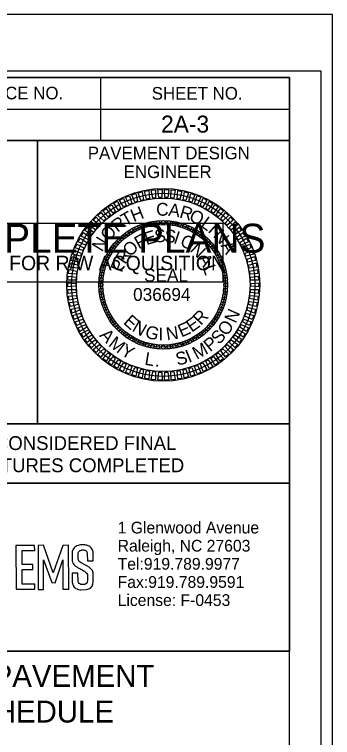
# Model space of a CAD drawing. Extents: x 958711 to 962106, y 831169 to 840840.
# Drawn here: x 960268.7 to 960394.8, y 838104 to 838391.1 of the extents above; entities that cross this region are included whole.
import ezdxf

# ---------------------------------------------------------------- set-up
doc = ezdxf.new("R2010")
doc.units = 0
for name, color, linetype in [('Old_Level_1', 7, 'Continuous'), ('Old_Level_2', 7, 'Continuous'), ('Old_Level_50', 7, 'Continuous'), ('Old_Level_58', 7, 'Continuous'), ('Sheet Data Field CELL', 7, 'Continuous'), ('Sheet PE Seal Cell', 7, 'Continuous'), ('Sheet Plot Border Inside CELL', 7, 'Continuous'), ('Sheet Plot Border Outside CELL', 7, 'Continuous'), ('Sheet Sticker Exception Certification CELL', 7, 'Continuous'), ('Sheet Sticker Incomplete CELL', 7, 'Continuous'), ('Sheet Typical CELL', 7, 'Continuous')]:
    doc.layers.add(name, color=color, linetype=linetype)

msp = doc.modelspace()

# ---------------------------------------------------------------- linework, layer by layer
at = {"layer": 'Old_Level_1'}
for points in [[(960276.67, 838180.33), (960269.28, 838180.32), (960269.3, 838162.89), (960276.77, 838162.9), (960276.77, 838164.87), (960271.73, 838164.87), (960271.72, 838170.71), (960275.94, 838170.71), (960275.93, 838172.79), (960271.68, 838172.78), (960271.68, 838178.28), (960276.69, 838178.29)], [(960284.05, 838169.48), (960280.23, 838180.4), (960278.02, 838180.29), (960278.11, 838162.83), (960280.22, 838162.84), (960280.16, 838174.52), (960283.43, 838165.53), (960284.78, 838165.5), (960287.84, 838174.63), (960287.89, 838162.91), (960290.17, 838162.92), (960290.1, 838180.34), (960287.8, 838180.33)], [(960297.57, 838174.17), (960299.88, 838174.17), (960299.88, 838177.65), (960299.69, 838178.35), (960299.4, 838178.94), (960299.11, 838179.33), (960298.74, 838179.69), (960298.3, 838179.97), (960297.87, 838180.14), (960297.87, 838180.14), (960297.41, 838180.34), (960296.93, 838180.46), (960296.61, 838180.54), (960294.86, 838180.5), (960294.33, 838180.41), (960293.87, 838180.33), (960293.41, 838180.09), (960293.01, 838179.88), (960292.61, 838179.6), (960292.3, 838179.28), (960292.06, 838178.92), (960291.87, 838178.52), (960291.61, 838177.83), (960291.56, 838177.31), (960291.56, 838174.14), (960291.68, 838173.67), (960291.91, 838173.17), (960292.19, 838172.76), (960292.49, 838172.45), (960292.94, 838172.1), (960293.39, 838171.76), (960293.68, 838171.54), (960294.16, 838171.31), (960294.65, 838171.09), (960295.04, 838170.83), (960295.48, 838170.55), (960296, 838170.28), (960296.44, 838170.06), (960296.87, 838169.75), (960297.18, 838169.45), (960297.43, 838169.21), (960297.58, 838168.73), (960297.67, 838168.43), (960297.64, 838166.2), (960297.48, 838165.71), (960297.23, 838165.29), (960296.91, 838165), (960296.55, 838164.84), (960296.21, 838164.77), (960295.25, 838164.75), (960294.93, 838164.84), (960294.6, 838165.03), (960294.27, 838165.23), (960294.13, 838165.56), (960293.98, 838165.9), (960293.87, 838166.16), (960293.83, 838169.28), (960291.5, 838169.25), (960291.54, 838165.54), (960291.66, 838165.26), (960291.93, 838164.39), (960292.1, 838164.1), (960292.36, 838163.78), (960292.74, 838163.41), (960293.04, 838163.22), (960293.48, 838163.03), (960293.63, 838162.97), (960294.06, 838162.79), (960294.6, 838162.73), (960294.99, 838162.69), (960297.13, 838162.75), (960297.73, 838162.89), (960298.55, 838163.26), (960298.83, 838163.39), (960299.45, 838164.18), (960299.79, 838164.97), (960299.94, 838165.68), (960299.89, 838169.1), (960299.88, 838169.57), (960299.75, 838169.95), (960299.56, 838170.3), (960299.02, 838171.06), (960298.31, 838171.62), (960297.34, 838172.2), (960296.59, 838172.64), (960295.13, 838173.41), (960294.37, 838173.97), (960294.05, 838174.39), (960293.97, 838174.67), (960293.89, 838174.96), (960293.94, 838177.39), (960294.06, 838177.64), (960294.19, 838177.9), (960294.36, 838178.05), (960294.59, 838178.25), (960294.85, 838178.35), (960295.11, 838178.46), (960295.26, 838178.43), (960295.27, 838178.51), (960296.23, 838178.49), (960296.51, 838178.38), (960296.79, 838178.27), (960297.07, 838178.16), (960297.19, 838177.97), (960297.38, 838177.69), (960297.47, 838177.41), (960297.56, 838177.14), (960297.56, 838176.83)]]:
    msp.add_lwpolyline(points, close=True, dxfattribs=at)
at = {"layer": 'Old_Level_50'}
msp.add_line((960177.74, 838138.32), (960377.79, 838138.32), dxfattribs=at)
at = {"layer": 'Old_Level_58'}
msp.add_lwpolyline([(960177.75, 838205.02), (960377.8, 838205.02), (960377.8, 838138.32), (960177.75, 838138.32)], close=True, dxfattribs=at)
at = {"layer": 'Sheet PE Seal Cell'}
for points in [[(960314.16, 838315.68), (960312.74, 838318.53), (960314.28, 838319.12), (960315.23, 838316.12)], [(960316.42, 838316.54), (960315.21, 838319.49), (960316.78, 838319.97), (960317.52, 838316.91)], [(960318.73, 838317.25), (960317.73, 838320.27), (960319.34, 838320.64), (960319.86, 838317.54)], [(960321.09, 838317.79), (960320.3, 838320.88), (960321.93, 838321.13), (960322.24, 838318)], [(960323.48, 838318.17), (960322.91, 838321.3), (960324.55, 838321.44), (960324.64, 838318.3)], [(960325.89, 838318.38), (960325.54, 838321.54), (960327.19, 838321.57), (960327.06, 838318.43)], [(960328.31, 838318.42), (960328.18, 838321.6), (960329.83, 838321.51), (960329.48, 838318.39)], [(960330.73, 838318.29), (960330.82, 838321.47), (960332.46, 838321.27), (960331.89, 838318.18)], [(960333.13, 838317.99), (960333.44, 838321.16), (960335.06, 838320.85), (960334.28, 838317.8)], [(960335.51, 838317.53), (960336.04, 838320.67), (960337.63, 838320.24), (960336.64, 838317.26)], [(960337.84, 838316.9), (960338.59, 838320), (960340.15, 838319.46), (960338.95, 838316.55)], [(960340.13, 838316.11), (960341.1, 838319.15), (960342.61, 838318.5), (960341.21, 838315.68)], [(960309.84, 838313.48), (960308.05, 838316.11), (960309.49, 838316.91), (960310.85, 838314.07)], [(960311.96, 838314.66), (960310.35, 838317.4), (960311.85, 838318.1), (960313.01, 838315.17)], [(960342.36, 838315.17), (960343.53, 838318.12), (960345, 838317.38), (960343.41, 838314.66)], [(960344.51, 838314.07), (960345.89, 838316.94), (960347.3, 838316.09), (960345.53, 838313.49)], [(960305.88, 838310.71), (960303.74, 838313.06), (960305.05, 838314.06), (960306.79, 838311.44)], [(960307.81, 838312.17), (960305.84, 838314.66), (960307.22, 838315.56), (960308.78, 838312.83)], [(960346.59, 838312.82), (960348.16, 838315.58), (960349.51, 838314.64), (960347.56, 838312.17)], [(960348.57, 838311.43), (960350.33, 838314.08), (960351.61, 838313.04), (960349.49, 838310.72)], [(960302.34, 838307.42), (960299.89, 838309.45), (960301.06, 838310.61), (960303.14, 838308.26)], [(960304.05, 838309.13), (960301.75, 838311.32), (960302.99, 838312.4), (960304.91, 838309.91)], [(960350.45, 838309.9), (960352.39, 838312.42), (960353.6, 838311.3), (960351.32, 838309.13)], [(960352.22, 838308.25), (960354.33, 838310.63), (960355.46, 838309.42), (960353.03, 838307.42)], [(960300.75, 838305.59), (960298.16, 838307.45), (960299.25, 838308.69), (960301.49, 838306.49)], [(960353.87, 838306.48), (960356.14, 838308.71), (960357.18, 838307.42), (960354.62, 838305.59)], [(960297.97, 838301.63), (960295.15, 838303.11), (960296.05, 838304.49), (960298.58, 838302.62)], [(960299.29, 838303.66), (960296.58, 838305.33), (960297.58, 838306.64), (960299.97, 838304.61)], [(960355.39, 838304.6), (960357.82, 838306.66), (960358.76, 838305.31), (960356.08, 838303.66)], [(960356.78, 838302.62), (960359.34, 838304.5), (960360.19, 838303.09), (960357.4, 838301.63)], [(960296.8, 838299.51), (960293.88, 838300.79), (960294.68, 838302.23), (960297.34, 838300.55)], [(960358.02, 838300.54), (960360.71, 838302.24), (960361.46, 838300.77), (960358.57, 838299.51)], [(960295.77, 838297.32), (960292.78, 838298.39), (960293.47, 838299.88), (960296.24, 838298.39)], [(960359.12, 838298.38), (960361.92, 838299.89), (960362.56, 838298.38), (960359.6, 838297.32)], [(960294.91, 838295.06), (960291.84, 838295.92), (960292.43, 838297.46), (960295.3, 838296.16)], [(960360.06, 838296.15), (960362.96, 838297.47), (960363.5, 838295.91), (960360.47, 838295.06)], [(960294.2, 838292.75), (960291.08, 838293.39), (960291.56, 838294.97), (960294.51, 838293.87)], [(960360.85, 838293.87), (960363.83, 838294.97), (960364.26, 838293.38), (960361.18, 838292.75)], [(960293.65, 838290.39), (960290.5, 838290.81), (960290.87, 838292.42), (960293.89, 838291.53)], [(960361.47, 838291.53), (960364.53, 838292.42), (960364.84, 838290.8), (960361.72, 838290.39)], [(960293.06, 838285.59), (960289.87, 838285.57), (960290.02, 838287.21), (960293.13, 838286.75)], [(960293.27, 838288), (960290.09, 838288.2), (960290.35, 838289.83), (960293.42, 838289.15)], [(960361.93, 838289.15), (960365.04, 838289.83), (960365.24, 838288.2), (960362.1, 838288)], [(960362.23, 838286.75), (960365.38, 838287.21), (960365.46, 838285.56), (960362.32, 838285.59)], [(960293.01, 838283.17), (960289.84, 838282.93), (960289.87, 838284.58), (960293.01, 838284.33)], [(960362.35, 838284.33), (960365.53, 838284.57), (960365.5, 838282.92), (960362.36, 838283.17)], [(960293.14, 838280.75), (960289.99, 838280.29), (960289.9, 838281.94), (960293.05, 838281.91)], [(960362.31, 838281.91), (960365.49, 838281.93), (960365.35, 838280.29), (960362.23, 838280.75)], [(960293.43, 838278.35), (960290.32, 838277.67), (960290.12, 838279.31), (960293.26, 838279.5)], [(960362.1, 838279.5), (960365.27, 838279.3), (960365.01, 838277.67), (960361.94, 838278.35)], [(960293.89, 838275.97), (960290.84, 838275.08), (960290.52, 838276.7), (960293.64, 838277.11)], [(960361.72, 838277.11), (960364.87, 838276.69), (960364.5, 838275.08), (960361.48, 838275.97)], [(960294.52, 838273.64), (960291.53, 838272.53), (960291.11, 838274.12), (960294.19, 838274.75)], [(960361.17, 838274.75), (960364.29, 838274.11), (960363.8, 838272.53), (960360.86, 838273.63)], [(960295.3, 838271.35), (960292.4, 838270.03), (960291.87, 838271.59), (960294.9, 838272.44)], [(960296.25, 838269.12), (960293.45, 838267.61), (960292.8, 838269.12), (960295.77, 838270.18)], [(960359.59, 838270.18), (960362.59, 838269.11), (960361.89, 838267.62), (960359.12, 838269.11)], [(960360.46, 838272.44), (960363.53, 838271.58), (960362.93, 838270.04), (960360.07, 838271.34)], [(960297.34, 838266.96), (960294.66, 838265.26), (960293.91, 838266.73), (960296.79, 838267.99)], [(960358.57, 838267.99), (960361.48, 838266.71), (960360.68, 838265.27), (960358.03, 838266.96)], [(960298.59, 838264.89), (960296.03, 838263), (960295.18, 838264.41), (960297.97, 838265.87)], [(960357.39, 838265.87), (960360.21, 838264.39), (960359.31, 838263.01), (960356.78, 838264.88)], [(960299.98, 838262.9), (960297.55, 838260.84), (960296.61, 838262.19), (960299.29, 838263.84)], [(960301.5, 838261.02), (960299.22, 838258.79), (960298.19, 838260.08), (960300.74, 838261.91)], [(960354.61, 838261.91), (960357.2, 838260.06), (960356.12, 838258.81), (960353.87, 838261.01)], [(960356.07, 838263.84), (960358.78, 838262.17), (960357.79, 838260.86), (960355.39, 838262.9)], [(960303.15, 838259.25), (960301.03, 838256.87), (960299.91, 838258.08), (960302.33, 838260.08)], [(960353.03, 838260.09), (960355.48, 838258.05), (960354.31, 838256.89), (960352.22, 838259.24)], [(960304.92, 838257.6), (960302.97, 838255.08), (960301.77, 838256.2), (960304.05, 838258.37)], [(960306.8, 838256.07), (960305.03, 838253.42), (960303.75, 838254.46), (960305.87, 838256.78)], [(960349.49, 838256.79), (960351.63, 838254.44), (960350.31, 838253.44), (960348.57, 838256.07)], [(960351.31, 838258.38), (960353.62, 838256.18), (960352.37, 838255.1), (960350.45, 838257.59)], [(960308.78, 838254.68), (960307.2, 838251.92), (960305.85, 838252.86), (960307.81, 838255.33)], [(960310.85, 838253.44), (960309.47, 838250.57), (960308.06, 838251.42), (960309.84, 838254.01)], [(960313.01, 838252.34), (960311.83, 838249.38), (960310.36, 838250.13), (960311.96, 838252.84)], [(960343.4, 838252.84), (960345.01, 838250.1), (960343.52, 838249.4), (960342.36, 838252.33)], [(960345.52, 838254.02), (960347.32, 838251.39), (960345.87, 838250.59), (960344.52, 838253.43)], [(960347.55, 838255.33), (960349.53, 838252.84), (960348.14, 838251.94), (960346.59, 838254.68)], [(960315.23, 838251.39), (960314.27, 838248.35), (960312.75, 838249), (960314.15, 838251.82)], [(960317.52, 838250.6), (960316.77, 838247.5), (960315.21, 838248.04), (960316.41, 838250.95)], [(960319.86, 838249.97), (960319.33, 838246.83), (960317.73, 838247.26), (960318.73, 838250.25)], [(960336.63, 838250.25), (960337.64, 838247.23), (960336.03, 838246.86), (960335.51, 838249.96)], [(960338.95, 838250.96), (960340.16, 838248.01), (960338.58, 838247.53), (960337.84, 838250.59)], [(960341.21, 838251.82), (960342.62, 838248.97), (960341.08, 838248.38), (960340.13, 838251.38)], [(960322.24, 838249.51), (960321.92, 838246.34), (960320.3, 838246.65), (960321.09, 838249.7)], [(960324.64, 838249.21), (960324.55, 838246.03), (960322.91, 838246.23), (960323.48, 838249.32)], [(960327.05, 838249.08), (960327.18, 838245.9), (960325.54, 838245.99), (960325.89, 838249.12)], [(960329.47, 838249.12), (960329.83, 838245.96), (960328.18, 838245.93), (960328.31, 838249.07)], [(960331.88, 838249.33), (960332.46, 838246.2), (960330.81, 838246.06), (960330.73, 838249.2)], [(960334.28, 838249.71), (960335.06, 838246.62), (960333.44, 838246.37), (960333.13, 838249.5)]]:
    msp.add_lwpolyline(points, close=True, dxfattribs=at)
for centre, radius in [((960327.68, 838283.75), 38.25), ((960327.68, 838283.75), 36.34), ((960327.68, 838283.75), 34.43), ((960327.68, 838283.75), 25.5), ((960327.68, 838283.75), 24.74), ((960327.68, 838283.75), 23.97), ((960319.22, 838307), 0.765), ((960321.28, 838307.64), 0.765), ((960323.39, 838308.11), 0.765), ((960325.53, 838308.39), 0.765), ((960327.68, 838308.49), 0.765), ((960329.84, 838308.39), 0.765), ((960331.98, 838308.11), 0.765), ((960334.09, 838307.64), 0.765), ((960336.14, 838307), 0.765), ((960313.49, 838304.01), 0.765), ((960315.31, 838305.17), 0.765), ((960317.23, 838306.17), 0.765), ((960338.14, 838306.17), 0.765), ((960340.05, 838305.17), 0.765), ((960341.87, 838304.01), 0.765), ((960310.19, 838301.24), 0.765), ((960311.78, 838302.7), 0.765), ((960343.58, 838302.7), 0.765), ((960345.17, 838301.24), 0.765), ((960307.42, 838297.94), 0.765), ((960308.73, 838299.65), 0.765), ((960346.63, 838299.65), 0.765), ((960347.95, 838297.94), 0.765), ((960306.26, 838296.12), 0.765), ((960349.11, 838296.12), 0.765), ((960304.44, 838292.21), 0.765), ((960305.26, 838294.2), 0.765), ((960350.1, 838294.2), 0.765), ((960350.93, 838292.21), 0.765), ((960303.79, 838290.15), 0.765), ((960351.58, 838290.15), 0.765), ((960303.32, 838288.05), 0.765), ((960352.04, 838288.05), 0.765), ((960302.95, 838283.75), 0.765), ((960303.04, 838285.91), 0.765), ((960352.33, 838285.91), 0.765), ((960352.42, 838283.75), 0.765), ((960303.04, 838281.59), 0.765), ((960352.33, 838281.59), 0.765), ((960303.32, 838279.45), 0.765), ((960352.04, 838279.45), 0.765), ((960303.79, 838277.35), 0.765), ((960304.44, 838275.29), 0.765), ((960350.93, 838275.29), 0.765), ((960351.58, 838277.35), 0.765), ((960305.26, 838273.3), 0.765), ((960350.1, 838273.3), 0.765), ((960306.26, 838271.38), 0.765), ((960307.42, 838269.56), 0.765), ((960347.95, 838269.56), 0.765), ((960349.11, 838271.38), 0.765), ((960308.73, 838267.85), 0.765), ((960346.63, 838267.85), 0.765), ((960310.19, 838266.26), 0.765), ((960311.78, 838264.8), 0.765), ((960313.49, 838263.49), 0.765), ((960341.87, 838263.49), 0.765), ((960343.58, 838264.8), 0.765), ((960345.17, 838266.26), 0.765), ((960315.31, 838262.33), 0.765), ((960317.23, 838261.33), 0.765), ((960338.14, 838261.33), 0.765), ((960340.05, 838262.33), 0.765), ((960319.22, 838260.5), 0.765), ((960321.28, 838259.86), 0.765), ((960323.39, 838259.39), 0.765), ((960325.53, 838259.11), 0.765), ((960327.68, 838259.01), 0.765), ((960329.84, 838259.11), 0.765), ((960331.98, 838259.39), 0.765), ((960334.09, 838259.86), 0.765), ((960336.14, 838260.5), 0.765)]:
    msp.add_circle(centre, radius, dxfattribs=at)
at = {"layer": 'Sheet Plot Border Inside CELL'}
msp.add_lwpolyline([(960390.3, 838368.62), (958723.8, 838368.62), (958723.8, 837313.52), (960390.3, 837313.52)], close=True, dxfattribs=at)
at = {"layer": 'Sheet Plot Border Outside CELL'}
msp.add_lwpolyline([(960394.8, 838391.07), (958710.8, 838391.07), (958710.8, 837291.07), (960394.8, 837291.07)], close=True, dxfattribs=at)
at = {"layer": 'Sheet Sticker Exception Certification CELL'}
for p, q in [((960177.75, 838228.52), (960377.79, 838228.52)), ((960377.79, 838228.5), (960377.79, 838205)), ((960377.79, 838205.02), (960177.75, 838205.02))]:
    msp.add_line(p, q, dxfattribs=at)
at = {"layer": 'Sheet Sticker Incomplete CELL'}
msp.add_lwpolyline([(960204.3, 838284.77), (960204.3, 838308.27), (960351.3, 838308.27), (960351.3, 838284.77)], close=True, dxfattribs=at)
at = {"layer": 'Sheet Typical CELL'}
for p, q in [((960302.8, 838366.02), (960302.8, 838341.02)), ((960177.75, 838353.52), (960377.8, 838353.52)), ((960277.8, 838341.02), (960277.8, 838228.57))]:
    msp.add_line(p, q, dxfattribs=at)
for points in [[(960377.8, 838366.07), (958877.8, 838366.07), (958877.8, 837316.07), (960377.8, 837316.07)], [(960177.75, 838366.07), (960377.8, 838366.07), (960377.8, 838341.02), (960177.75, 838341.02)], [(960177.75, 838341.02), (960277.8, 838341.02), (960277.8, 838228.52), (960177.75, 838228.52)], [(960277.8, 838341.02), (960377.8, 838341.02), (960377.8, 838228.52), (960277.8, 838228.52)]]:
    msp.add_lwpolyline(points, close=True, dxfattribs=at)

# ---------------------------------------------------------------- texts
at = {"layer": 'Old_Level_1'}
for s, rotation, p in [('N', 66.0368, (960356.35, 838268.2)), ('O', 55.3117, (960352.96, 838263.13)), ('A', 312.9092, (960302.12, 838263.49)), ('S', 47.1983, (960349.8, 838259.77)), ('M', 321.9567, (960305.62, 838259.72)), ('P', 39.2185, (960346.25, 838256.94)), ('Y', 332.6628, (960310.47, 838256.04)), ('M', 28.5124, (960340.95, 838253.95)), ('L', 351.0246, (960320.07, 838252.03)), ('S', 14.4591, (960333.32, 838251.62)), ('I', 22.5724, (960337.79, 838252.74)), ('.', 358.4898, (960324.26, 838251.31))]:
    msp.add_text(s, height=5.1, rotation=rotation, dxfattribs=at).set_placement(p)
at = {"layer": 'Old_Level_2'}
for s, p in [('1 Glenwood Avenue', (960309.6, 838185.05)), ('Raleigh, NC 27603', (960309.6, 838177.86)), ('Tel:919.789.9977 ', (960309.6, 838170.66)), ('Fax:919.789.9591', (960309.6, 838163.46)), ('License: F-0453', (960309.6, 838156.27))]:
    msp.add_text(s, height=4.6576, rotation=360, dxfattribs=at).set_placement(p)
at = {"layer": 'Old_Level_50'}
for s, height, p in [('FINAL PAVEMENT', 8.7206, (960223.74, 838124.16)), ('SCHEDULE', 8.721, (960244.65, 838109.99))]:
    msp.add_text(s, height=height, dxfattribs=at).set_placement(p)
at = {"layer": 'Sheet Data Field CELL'}
msp.add_text('2A-3', height=6.75, dxfattribs=at).set_placement((960326.81, 838344.17))
at = {"layer": 'Sheet PE Seal Cell'}
for s, rotation, p in [('C', 1.9618, (960324.96, 838311.09)), ('A', 352.4568, (960329.51, 838311.16)), ('T', 29.3903, (960312.67, 838306.76)), ('H', 21.601, (960315.93, 838308.58)), ('R', 343.4093, (960333.8, 838310.53)), ('O', 335.2006, (960337.56, 838309.39)), ('R', 37.5989, (960309.54, 838304.38)), ('L', 324.4755, (960342.16, 838307.1)), ('I', 317.0103, (960345.07, 838305.02)), ('O', 48.3241, (960306.02, 838300.65)), ('E', 16.986, (960321.02, 838299.45)), ('S', 5.2237, (960324.36, 838300.48)), ('S', 353.2648, (960327.9, 838300.8)), ('I', 341.3058, (960331.43, 838300.39)), ('N', 311.0704, (960347.18, 838303.11)), ('N', 58.5345, (960303.37, 838296.54)), ('F', 28.6639, (960317.98, 838297.77)), ('O', 332.5504, (960333.92, 838299.62)), ('O', 44.4727, (960314.53, 838294.6)), ('N', 316.7416, (960338, 838297.32)), ('A', 300.8599, (960350.3, 838299.35)), ('R', 56.5721, (960312.55, 838291.6)), ('P', 68.3344, (960311.26, 838288.35)), ('A', 301.6915, (960341.18, 838294.18)), ('L', 288.3556, (960343.22, 838290.79)), ('R', 47.043, (960342.61, 838267.41)), ('E', 317.8506, (960311.56, 838268.59)), ('E', 35.2807, (960338.97, 838264.71)), ('N', 329.6129, (960314.98, 838265.62)), ('G', 344.6629, (960320.13, 838262.95)), ('N', 8.4684, (960329.17, 838261.67)), ('E', 23.5185, (960334.85, 838262.81)), ('I', 359.713, (960325.79, 838261.7))]:
    msp.add_text(s, height=5.1, rotation=rotation, dxfattribs=at).set_placement(p)
for s, p in [('SEAL', (960320.06, 838285.03)), ('036694', (960315.72, 838277.37))]:
    msp.add_text(s, height=5.101, dxfattribs=at).set_placement(p)
at = {"layer": 'Sheet Sticker Exception Certification CELL'}
for s, p in [('DOCUMENT NOT CONSIDERED FINAL', (960198.82, 838218.17)), ('UNLESS ALL SIGNATURES COMPLETED', (960193.75, 838209.37))]:
    msp.add_text(s, height=5.5, dxfattribs=at).set_placement(p)
at = {"layer": 'Sheet Sticker Incomplete CELL'}
for s, height, p in [('INCOMPLETE PLANS', 11.52, (960213.25, 838296.47)), ('DO NOT USE FOR R/W ACQUISITION', 5.76, (960216.5, 838289.52))]:
    msp.add_text(s, height=height, dxfattribs=at).set_placement(p)
at = {"layer": 'Sheet Typical CELL'}
for s, height, p in [('PROJECT REFERENCE NO.', 5.0001, (960199.95, 838357.37)), ('SHEET NO.', 5, (960323.1, 838357.27)), ('PAVEMENT DESIGN', 5.0001, (960297.75, 838333.57)), ('ENGINEER', 5, (960311.95, 838326.12))]:
    msp.add_text(s, height=height, dxfattribs=at).set_placement(p)

doc.saveas('drawing.dxf')
